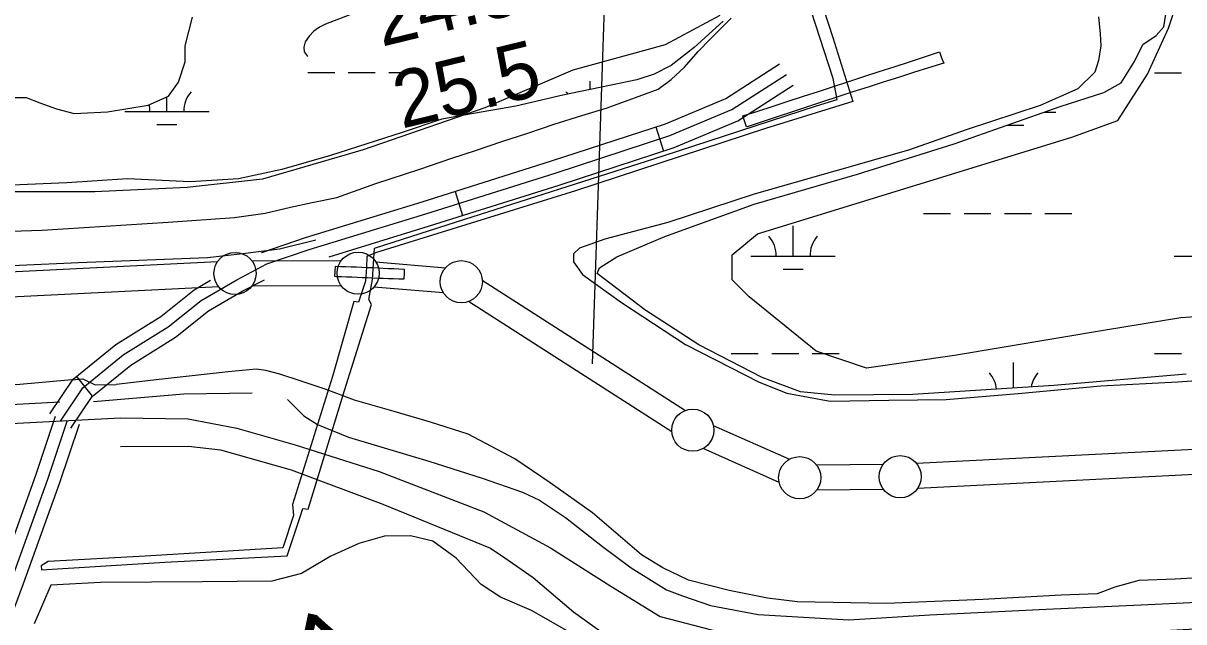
# Model space of a CAD drawing. Extents: x 3297772 to 3335630, y 634068 to 659439.
# Drawn here: x 3331326 to 3332702, y 644761 to 645471 of the extents above; entities that cross this region are included whole.
import ezdxf

# ---------------------------------------------------------------- set-up
doc = ezdxf.new("R2010")
doc.units = 0
for name, color, linetype in [('V-BRDG-OTLN', 7, 'Continuous'), ('V-DTCH-CNTR', 7, 'Continuous'), ('V-FLOD-BASE', 7, 'Continuous'), ('V-LEVE-TOET', 7, 'Continuous'), ('V-RIVR-RANG', 7, 'Continuous'), ('V-ROAD-CNTR', 7, 'Continuous'), ('V-SITE-STRC', 7, 'Continuous'), ('V-SITE-VEGE', 7, 'Continuous'), ('V-SURV-IDEN', 7, 'Continuous'), ('V-SURV-LINE', 7, 'Continuous'), ('V-TOPO-MAJR', 7, 'Continuous'), ('V-TOPO-SHOR', 7, 'Continuous'), ('V-UTIL-LINE', 7, 'Continuous'), ('V-WETL-SWMP', 7, 'Continuous')]:
    doc.layers.add(name, color=color, linetype=linetype)

msp = doc.modelspace()

# ---------------------------------------------------------------- linework, layer by layer
at = {"layer": 'V-BRDG-OTLN'}
msp.add_lwpolyline([(3331695.2, 645170.3), (3331695.5, 645176.5), (3331695.7, 645182.7), (3331701.9, 645182.5), (3331708.2, 645182.3), (3331714.4, 645182), (3331720.7, 645181.8), (3331727.1, 645181.6), (3331733.4, 645181.3), (3331739.7, 645181), (3331746, 645180.7), (3331752.3, 645180.4), (3331758.6, 645180.1), (3331764.9, 645179.8), (3331771.1, 645179.5), (3331777.2, 645179.1), (3331777.1, 645173.6), (3331776.9, 645168), (3331776.9, 645167.2), (3331770.8, 645167.4), (3331764.7, 645167.6), (3331758.6, 645167.8), (3331752.4, 645168.1), (3331746.2, 645168.3), (3331740, 645168.5), (3331733.8, 645168.7), (3331727.6, 645169), (3331721.4, 645169.2), (3331715.3, 645169.5), (3331709.1, 645169.7), (3331703, 645170), (3331696.9, 645170.2)], close=True, dxfattribs=at)
at = {"layer": 'V-DTCH-CNTR'}
msp.add_lwpolyline([(3331970.7, 644750.5), (3331928.3, 644774.7), (3331891.4, 644790.3), (3331868.4, 644805.5), (3331838.9, 644836.6), (3331811.3, 644856.9), (3331784.9, 644863.2), (3331753.8, 644862.8), (3331723.4, 644853.9), (3331690.3, 644838.8), (3331655.7, 644818.6), (3331620.3, 644809.3), (3331538.2, 644808.6), (3331417.3, 644807.6), (3331358.2, 644804.5), (3331338.7, 644758.7)], dxfattribs=at)
at = {"layer": 'V-FLOD-BASE'}
msp.add_lwpolyline([(3329075.4, 645065.6), (3329181.4, 645069.7), (3329301, 645075.7), (3329468.5, 645084.8), (3329631.1, 645097.4), (3329730.9, 645103.5), (3329836.9, 645110.3), (3329923.2, 645113.3), (3329989.4, 645114), (3330118.2, 645120.5), (3330263.3, 645126.1), (3330354.7, 645130.2), (3330498.2, 645135.5), (3330678.5, 645148.4), (3330866.2, 645157.5), (3330964.5, 645165.1), (3331115.4, 645173.9), (3331250.8, 645180.7), (3331391.3, 645187.1), (3331544.1, 645193.1), (3331585.9, 645197.7), (3331629.3, 645203.4), (3331672.6, 645213.8)], dxfattribs=at)
at = {"layer": 'V-LEVE-TOET'}
for points in [[(3332600.5, 645478.1), (3332602.4, 645458.2), (3332603.5, 645443.7), (3332600.4, 645426.5), (3332596.1, 645412.8), (3332576.1, 645392.9), (3332531.5, 645373), (3332444.7, 645344.6), (3332375.4, 645320.4), (3332287.8, 645295.5), (3332192.4, 645268.2), (3332089.9, 645234.3), (3332015.2, 645214.9), (3331985.1, 645204), (3331978, 645197.3), (3331978, 645187.9), (3331988.9, 645172.7), (3332035, 645139.8), (3332110.8, 645090), (3332198.4, 645045.4), (3332231.2, 645032), (3332282.4, 645022.6), (3332352, 645023.7), (3332420.1, 645024.8), (3332505.3, 645031.7), (3332603.5, 645041), (3332694.6, 645045.6), (3332938.6, 645062.9)], [(3331222.6, 645221.3), (3331348.1, 645225.4), (3331497.5, 645235), (3331576.1, 645240.4), (3331612.5, 645245.5), (3331642.6, 645252.5), (3331668, 645258.3), (3331697.3, 645264.1), (3331742.7, 645280.5), (3331795.9, 645297.6), (3331833.9, 645310.9), (3331862, 645319.9), (3331892.9, 645330.4), (3331923.8, 645340.5), (3331955.1, 645351), (3331988, 645361.2), (3332016.9, 645370.1), (3332039.6, 645378.3), (3332078.3, 645392.7), (3332094, 645404), (3332109.7, 645418.5), (3332125.7, 645437.2), (3332140.2, 645451.7), (3332165.2, 645476.7)], [(3332801.3, 644817.9), (3332691.4, 644811.8), (3332648.4, 644810.3), (3332619.8, 644802.1), (3332599.1, 644794.3), (3332556.5, 644792.8), (3332463.4, 644787.8), (3332349.2, 644782.9), (3332243.6, 644785), (3332208.1, 644789.3), (3332162.7, 644798.4), (3332114.6, 644810.5), (3332084.1, 644825), (3332058.8, 644840.7), (3332000.5, 644890.4), (3331950.5, 644926.1), (3331908.7, 644954.3), (3331853.2, 644983.7), (3331808.7, 644997.8), (3331765.3, 645010.4), (3331718.4, 645023.7), (3331684.8, 645036.7), (3331655.1, 645046.5), (3331629.7, 645054.7), (3331613.2, 645059), (3331601.9, 645060.6), (3331568.7, 645057.5), (3331486.9, 645048.2), (3331435.7, 645042.4)], [(3331383.3, 645048), (3331317.2, 645042.2), (3331246.1, 645045.4), (3331155.3, 645043.5), (3331052.1, 645038.6), (3330945, 645033.2), (3330861.7, 645031), (3330772.5, 645026), (3330689.6, 645022.2), (3330600.4, 645009.8)], [(3331383.3, 645048), (3331396.1, 645049.2), (3331410.7, 645042.1), (3331435.7, 645042.4)]]:
    msp.add_lwpolyline(points, dxfattribs=at)
at = {"layer": 'V-RIVR-RANG'}
msp.add_line((3332000.7, 645067.1), (3332047, 646450.3), dxfattribs=at)
at = {"layer": 'V-ROAD-CNTR'}
for p, q in [((3332075.6, 645347.7), (3332084.8, 645319.1)), ((3331837.6, 645271.4), (3331846.6, 645242.8)), ((3331388.6, 645051.9), (3331407.5, 645028.6))]:
    msp.add_line(p, q, dxfattribs=at)
for points in [[(3331608.2, 645198.9), (3331608.7, 645199.1), (3331660.2, 645216.7), (3331798.5, 645259), (3331951.8, 645307.4), (3332087.1, 645351.4), (3332158.8, 645381.6), (3332222.5, 645422.4)], [(3331369.7, 644999.2), (3331396.1, 645038.7), (3331444.2, 645077.5), (3331497.3, 645111), (3331536.7, 645142.2), (3331578.8, 645166.5), (3331614.6, 645185.3), (3331664.8, 645202.4), (3331802.9, 645244.7), (3331956.4, 645293.1), (3332092.4, 645337.4), (3332165.8, 645368.3), (3332230.6, 645409.7)], [(3331688.2, 645193.9), (3331807.4, 645230.4), (3331961, 645278.8), (3332097.6, 645323.3), (3332172.9, 645355), (3332238.7, 645397.1)], [(3331357.2, 645007.6), (3331384.9, 645048.9), (3331435.5, 645089.7), (3331488.6, 645123.2), (3331528.2, 645154.7), (3331547.8, 645166)], [(3331382.1, 644990.9), (3331407.3, 645028.4), (3331453, 645065.3), (3331506, 645098.7), (3331545.1, 645129.8), (3331586, 645153.3), (3331611.5, 645166.7)], [(3331377.7, 644999.7), (3331354.2, 644929.8), (3331311.5, 644811.3), (3331257.8, 644667.3), (3331227.6, 644585.4), (3331200.8, 644505.1), (3331116.1, 644248.6), (3330933.1, 643667.9), (3330742.9, 643076.2), (3330534.9, 642422.4)], [(3331179.9, 644989.5), (3331441, 645002.9), (3331521.1, 645001.9), (3331578.7, 644990.8), (3331648, 644970.9), (3331747.7, 644939.4), (3331871.6, 644891.7), (3331950.6, 644848.9), (3332022.3, 644803.4), (3332081, 644767.4), (3332152.5, 644748.8), (3332215.7, 644734.7), (3332344.8, 644731.4), (3332641.7, 644748.8), (3332937.5, 644764.7), (3333291.4, 644784.2), (3333441.9, 644790.5)], [(3331363.5, 645004.4), (3331340, 644934.8), (3331297.5, 644816.5), (3331254.7, 644701.9)], [(3331391.9, 644994.9), (3331368.3, 644924.9), (3331325.6, 644806.2), (3331271.9, 644662), (3331241.7, 644580.4), (3331215.1, 644500.4), (3331130.3, 644244), (3330947.4, 643663.4), (3330757.2, 643071.6), (3330549.2, 642417.8)]]:
    msp.add_lwpolyline(points, dxfattribs=at)
at = {"layer": 'V-SITE-STRC'}
msp.add_lwpolyline([(3332178.8, 645360.9), (3332196.8, 645366.6), (3332214.7, 645372.5), (3332232.7, 645378.3), (3332250.6, 645384.1), (3332268.6, 645389.9), (3332286.5, 645395.8), (3332304.5, 645401.6), (3332322.4, 645407.4), (3332340.4, 645413.3), (3332358.3, 645419.1), (3332376.3, 645425), (3332394.2, 645430.9), (3332412.1, 645436.7), (3332413.6, 645432.2), (3332415.3, 645427.8), (3332417.2, 645423.4), (3332399.2, 645417.8), (3332381.2, 645412.1), (3332363.3, 645406.4), (3332345.3, 645400.7), (3332327.3, 645394.9), (3332309.3, 645389.2), (3332291.4, 645383.3), (3332273.4, 645377.5), (3332255.5, 645371.6), (3332237.6, 645365.7), (3332219.7, 645359.8), (3332201.8, 645353.9), (3332183.9, 645347.9), (3332183.1, 645347.7), (3332178.8, 645360.9)], dxfattribs=at)
at = {"layer": 'V-SITE-VEGE'}
for p, q in [((3332683.4, 645464.9), (3332693.3, 645494.7)), ((3332151.4, 645479.8), (3332086.8, 645445)), ((3332658.5, 645410.2), (3332683.4, 645464.9)), ((3332086.8, 645445), (3331977.4, 645415.1)), ((3331977.4, 645415.1), (3331873, 645370.4)), ((3332623.7, 645355.4), (3332658.5, 645410.2)), ((3331873, 645370.4), (3331728.8, 645320.6)), ((3332569, 645335.5), (3332623.7, 645355.4)), ((3332196.2, 645221.1), (3332569, 645335.5)), ((3331728.8, 645320.6), (3331609.5, 645285.8)), ((3331609.5, 645285.8), (3331520, 645275.9)), ((3331520, 645275.9), (3331410.6, 645270.9)), ((3331410.6, 645270.9), (3331286.4, 645270.9)), ((3332166.3, 645196.3), (3332196.2, 645221.1)), ((3332166.3, 645166.4), (3332166.3, 645196.3)), ((3332186.2, 645146.5), (3332166.3, 645166.4)), ((3332265.8, 645081.9), (3332186.2, 645146.5)), ((3332698.3, 645121.6), (3332608.8, 645106.7)), ((3332772.9, 645126.6), (3332698.3, 645121.6)), ((3332608.8, 645106.7), (3332429.8, 645076.9)), ((3332325.4, 645062), (3332265.8, 645081.9)), ((3332429.8, 645076.9), (3332325.4, 645062))]:
    msp.add_line(p, q, dxfattribs=at)
at = {"layer": 'V-SURV-LINE'}
for points in [[(3331596.7, 645189.2), (3331702.7, 645189.3)], [(3329001, 645061.3), (3331556, 645188.1)], [(3331743.8, 645187.7), (3331826.3, 645180.9)], [(3331869.9, 645166.1), (3332110.8, 645011.8)], [(3331557.5, 645158.2), (3329002.4, 645031.3)], [(3331702.8, 645159.3), (3331596.7, 645159.2)], [(3331823.8, 645151), (3331741.4, 645157.8)], [(3332094.6, 644986.5), (3331853.7, 645140.9)], [(3332384.6, 644949.2), (3333444, 645002.7)], [(3332143.8, 644993.9), (3332234.2, 644953.8)], [(3333444, 644972.7), (3332386.1, 644919.2)], [(3332222, 644926.4), (3332131.7, 644966.5)], [(3332266.2, 644947.2), (3332345.3, 644948)], [(3332345.6, 644918), (3332266.5, 644917.2)]]:
    msp.add_lwpolyline(points, dxfattribs=at)
for centre in [(3331576.7, 645174.1), (3331722.7, 645174.4), (3331845, 645164.3), (3332119.5, 644988.3), (3332246.3, 644932), (3332365.4, 644933.2)]:
    msp.add_circle(centre, 25, dxfattribs=at)
at = {"layer": 'V-TOPO-MAJR'}
msp.add_lwpolyline([(3332053.9, 645488.9), (3332052.3, 645498.1), (3332048.8, 645508.2), (3332043.7, 645517), (3332036.2, 645523.8), (3332027, 645529.4), (3332016.3, 645533), (3332005.4, 645535.6), (3331994.2, 645536.9), (3331982.9, 645537.3), (3331881.3, 645534.4), (3331866, 645533.1), (3331850.8, 645530.9), (3331835.9, 645527.1), (3331821.3, 645522.3), (3331684.1, 645469.7), (3331676.7, 645465.9), (3331670.1, 645461.3), (3331664.6, 645455.4), (3331659.8, 645448.7), (3331658.3, 645442.3), (3331658.8, 645436.6), (3331662.2, 645432), (3331663.2, 645431.3)], dxfattribs=at)
at = {"layer": 'V-TOPO-SHOR'}
for points in [[(3331597, 645032), (3331516.1, 645030.9), (3331409.1, 645022.1)], [(3331639, 645024.5), (3331658.4, 645005.5), (3331674.7, 644994.9), (3331711.3, 644980.1), (3331806.5, 644951.6), (3331869.9, 644931.3), (3331917.7, 644914.9), (3331937.9, 644905.2), (3331968.6, 644884.9), (3332012.5, 644850.3), (3332046.3, 644825.3), (3332088.3, 644799.2)], [(3331369.1, 645021.4), (3331281.2, 645016.8), (3331150.9, 645013.1), (3331043.5, 645007.3), (3330894.2, 644997.8)], [(3331441.1, 644968.8), (3331521.6, 644969.4), (3331559.7, 644965.1), (3331643.3, 644941.3), (3331752.1, 644900.7), (3331879.6, 644848.5), (3331896.7, 644837.2), (3331930.1, 644813.8), (3331977.9, 644772.9), (3332031.5, 644734.7), (3332076.6, 644710.9), (3332105, 644699.2), (3332134.2, 644689.1), (3332169.6, 644683.6), (3332227.1, 644684.3), (3332297.9, 644687.3), (3332417.7, 644694.2), (3332544.1, 644699.1), (3332681.8, 644706), (3332756.8, 644707.8)], [(3332088.3, 644799.2), (3332107.4, 644791.8), (3332140.4, 644780.5), (3332197.2, 644769.9), (3332304.5, 644763.6), (3332400.6, 644769.3), (3332538.6, 644776.2), (3332651, 644781.5), (3332809.3, 644788.7)]]:
    msp.add_lwpolyline(points, dxfattribs=at)
at = {"layer": 'V-UTIL-LINE'}
msp.add_lwpolyline([(3332207.6, 645693.3), (3332285.4, 645453.7), (3332309.3, 645378), (3332205.6, 645345.9), (3331980.6, 645272), (3331743.4, 645198.4), (3331733.2, 645194.1), (3331732.8, 645181.6), (3331731.6, 645165.1), (3331723, 645140), (3331717.5, 645140.8), (3331692.2, 645052.1), (3331645, 644900.2), (3331646.1, 644887.3), (3331633.5, 644848.8), (3331470.2, 644838.8), (3331355.2, 644832.7), (3331346.9, 644827.6), (3331347.3, 644822.9), (3331493.4, 644831.7), (3331638.6, 644839.4), (3331653.6, 644884.5), (3331657.1, 644895.5), (3331663.4, 644894.7), (3331706.4, 645035.2), (3331738.7, 645137.2), (3331735.5, 645143.1), (3331739.9, 645167), (3331742.3, 645203.9), (3331829.5, 645232.1), (3332084.3, 645313.5), (3332266.1, 645372.9), (3332290.9, 645380.3), (3332285.8, 645405.1), (3332259.8, 645485.2)], dxfattribs=at)
at = {"layer": 'V-WETL-SWMP'}
for p, q in [((3332678.2, 645466.5), (3332680.9, 645483.8)), ((3332668.8, 645456.1), (3332678.2, 645466.5)), ((3332653.1, 645445.6), (3332668.8, 645456.1)), ((3332643.1, 645425.2), (3332653.1, 645445.6)), ((3332627.4, 645400.2), (3332643.1, 645425.2)), ((3331663, 645412.4), (3331695, 645412.4)), ((3331711, 645412.4), (3331743, 645412.4)), ((3331759, 645412.4), (3331791, 645412.4)), ((3332667, 645411.8), (3332699, 645411.8)), ((3331997.8, 645392.1), (3331997.8, 645402)), ((3332607, 645388.7), (3332627.4, 645400.2)), ((3331495.9, 645366), (3331495.9, 645383.3)), ((3332555.2, 645372), (3332607, 645388.7)), ((3332429.6, 645327.7), (3332555.2, 645372)), ((3331445.9, 645366), (3331545.9, 645366)), ((3332536.5, 645365.4), (3332549.9, 645365.4)), ((3331483.9, 645350.5), (3331507.9, 645350.5)), ((3332492.8, 645350), (3332511.9, 645350)), ((3332315, 645291.7), (3332429.6, 645327.7)), ((3332192.1, 645256.3), (3332315, 645291.7)), ((3332086.3, 645217.7), (3332192.1, 645256.3)), ((3332393.1, 645245.3), (3332425.1, 645245.3)), ((3332441.1, 645245.3), (3332473.1, 645245.3)), ((3332489.1, 645245.3), (3332521.1, 645245.3)), ((3332537.1, 645245.3), (3332569.1, 645245.3)), ((3332238.5, 645194.6), (3332238.5, 645230.6)), ((3332029.3, 645193.7), (3332086.3, 645217.7)), ((3332008.9, 645180.7), (3332029.3, 645193.7)), ((3332188.5, 645194.6), (3332288.5, 645194.6)), ((3332690.4, 645194.6), (3332790.4, 645194.6)), ((3332006.3, 645173.9), (3332008.9, 645180.7)), ((3332226.5, 645179.2), (3332250.5, 645179.2)), ((3332062.7, 645130.9), (3332006.3, 645173.9)), ((3332126.5, 645089.5), (3332062.7, 645130.9)), ((3332201.8, 645050.7), (3332126.5, 645089.5)), ((3332165.1, 645079.2), (3332197.1, 645079.2)), ((3332213.1, 645079.2), (3332245.1, 645079.2)), ((3332261.1, 645079.2), (3332293.1, 645079.2)), ((3332667, 645079.2), (3332699, 645079.2)), ((3332499.9, 645038.3), (3332499.9, 645068.7)), ((3332704.4, 645054.8), (3332547.5, 645041.4)), ((3332247.2, 645033.9), (3332201.8, 645050.7)), ((3332547.5, 645041.4), (3332380.6, 645030.6)), ((3332288, 645029.7), (3332247.2, 645033.9)), ((3332380.6, 645030.6), (3332288, 645029.7))]:
    msp.add_line(p, q, dxfattribs=at)
for points in [[(3331315.8, 645382.8), (3331329.1, 645382.7), (3331345.4, 645376.5), (3331364.9, 645369.1), (3331385.9, 645363.6), (3331425.7, 645365.5), (3331473.6, 645373.6), (3331497.8, 645384.1), (3331509.9, 645400.8), (3331517.7, 645425), (3331517.7, 645443.7), (3331526.3, 645478)], [(3332155.4, 645473.3), (3332121.1, 645441.8), (3332093.8, 645420.4), (3332073.9, 645410.3), (3332053.3, 645403.7), (3332032.2, 645399.1), (3331965.6, 645385.5), (3331909.5, 645372.3), (3331859.6, 645363.8), (3331821.8, 645356.9), (3331775.1, 645341.3), (3331690.1, 645313.8), (3331632.4, 645297.1), (3331581, 645286.2), (3331523.4, 645282.8), (3331449.3, 645286.4), (3331377.3, 645281.4), (3331293.1, 645278)]]:
    msp.add_lwpolyline(points, dxfattribs=at)
for centre, start, end in [((3331551.2, 645366.4), 139.2281, 180.7718), ((3331942.6, 645366.4), 35.0561, 40.7719), ((3331440.7, 645366.4), 359.2282, 12.7902), ((3332183.2, 645195.1), 359.2282, 40.7718), ((3332293.7, 645195.1), 139.2282, 180.7718), ((3332444.7, 645033.2), 6.2549, 40.7718), ((3332555.2, 645033.2), 139.2282, 169.4071)]:
    msp.add_arc(centre, 35.2, start, end, dxfattribs=at)

# ---------------------------------------------------------------- texts
at = {"layer": 'V-RIVR-RANG'}
for s, p in [('24.5', (3331750.4, 645442.6)), ('25.5', (3331774.3, 645345.5))]:
    msp.add_text(s, height=67, rotation=13.7183, dxfattribs=at).set_placement(p)
at = {"layer": 'V-SURV-IDEN'}
msp.add_text('4715+16.7', height=100, rotation=78.2995, dxfattribs=at).set_placement((3331633.8, 644135))

doc.saveas('drawing.dxf')
